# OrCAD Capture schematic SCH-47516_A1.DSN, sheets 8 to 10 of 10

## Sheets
8 Link2 ISP: size C
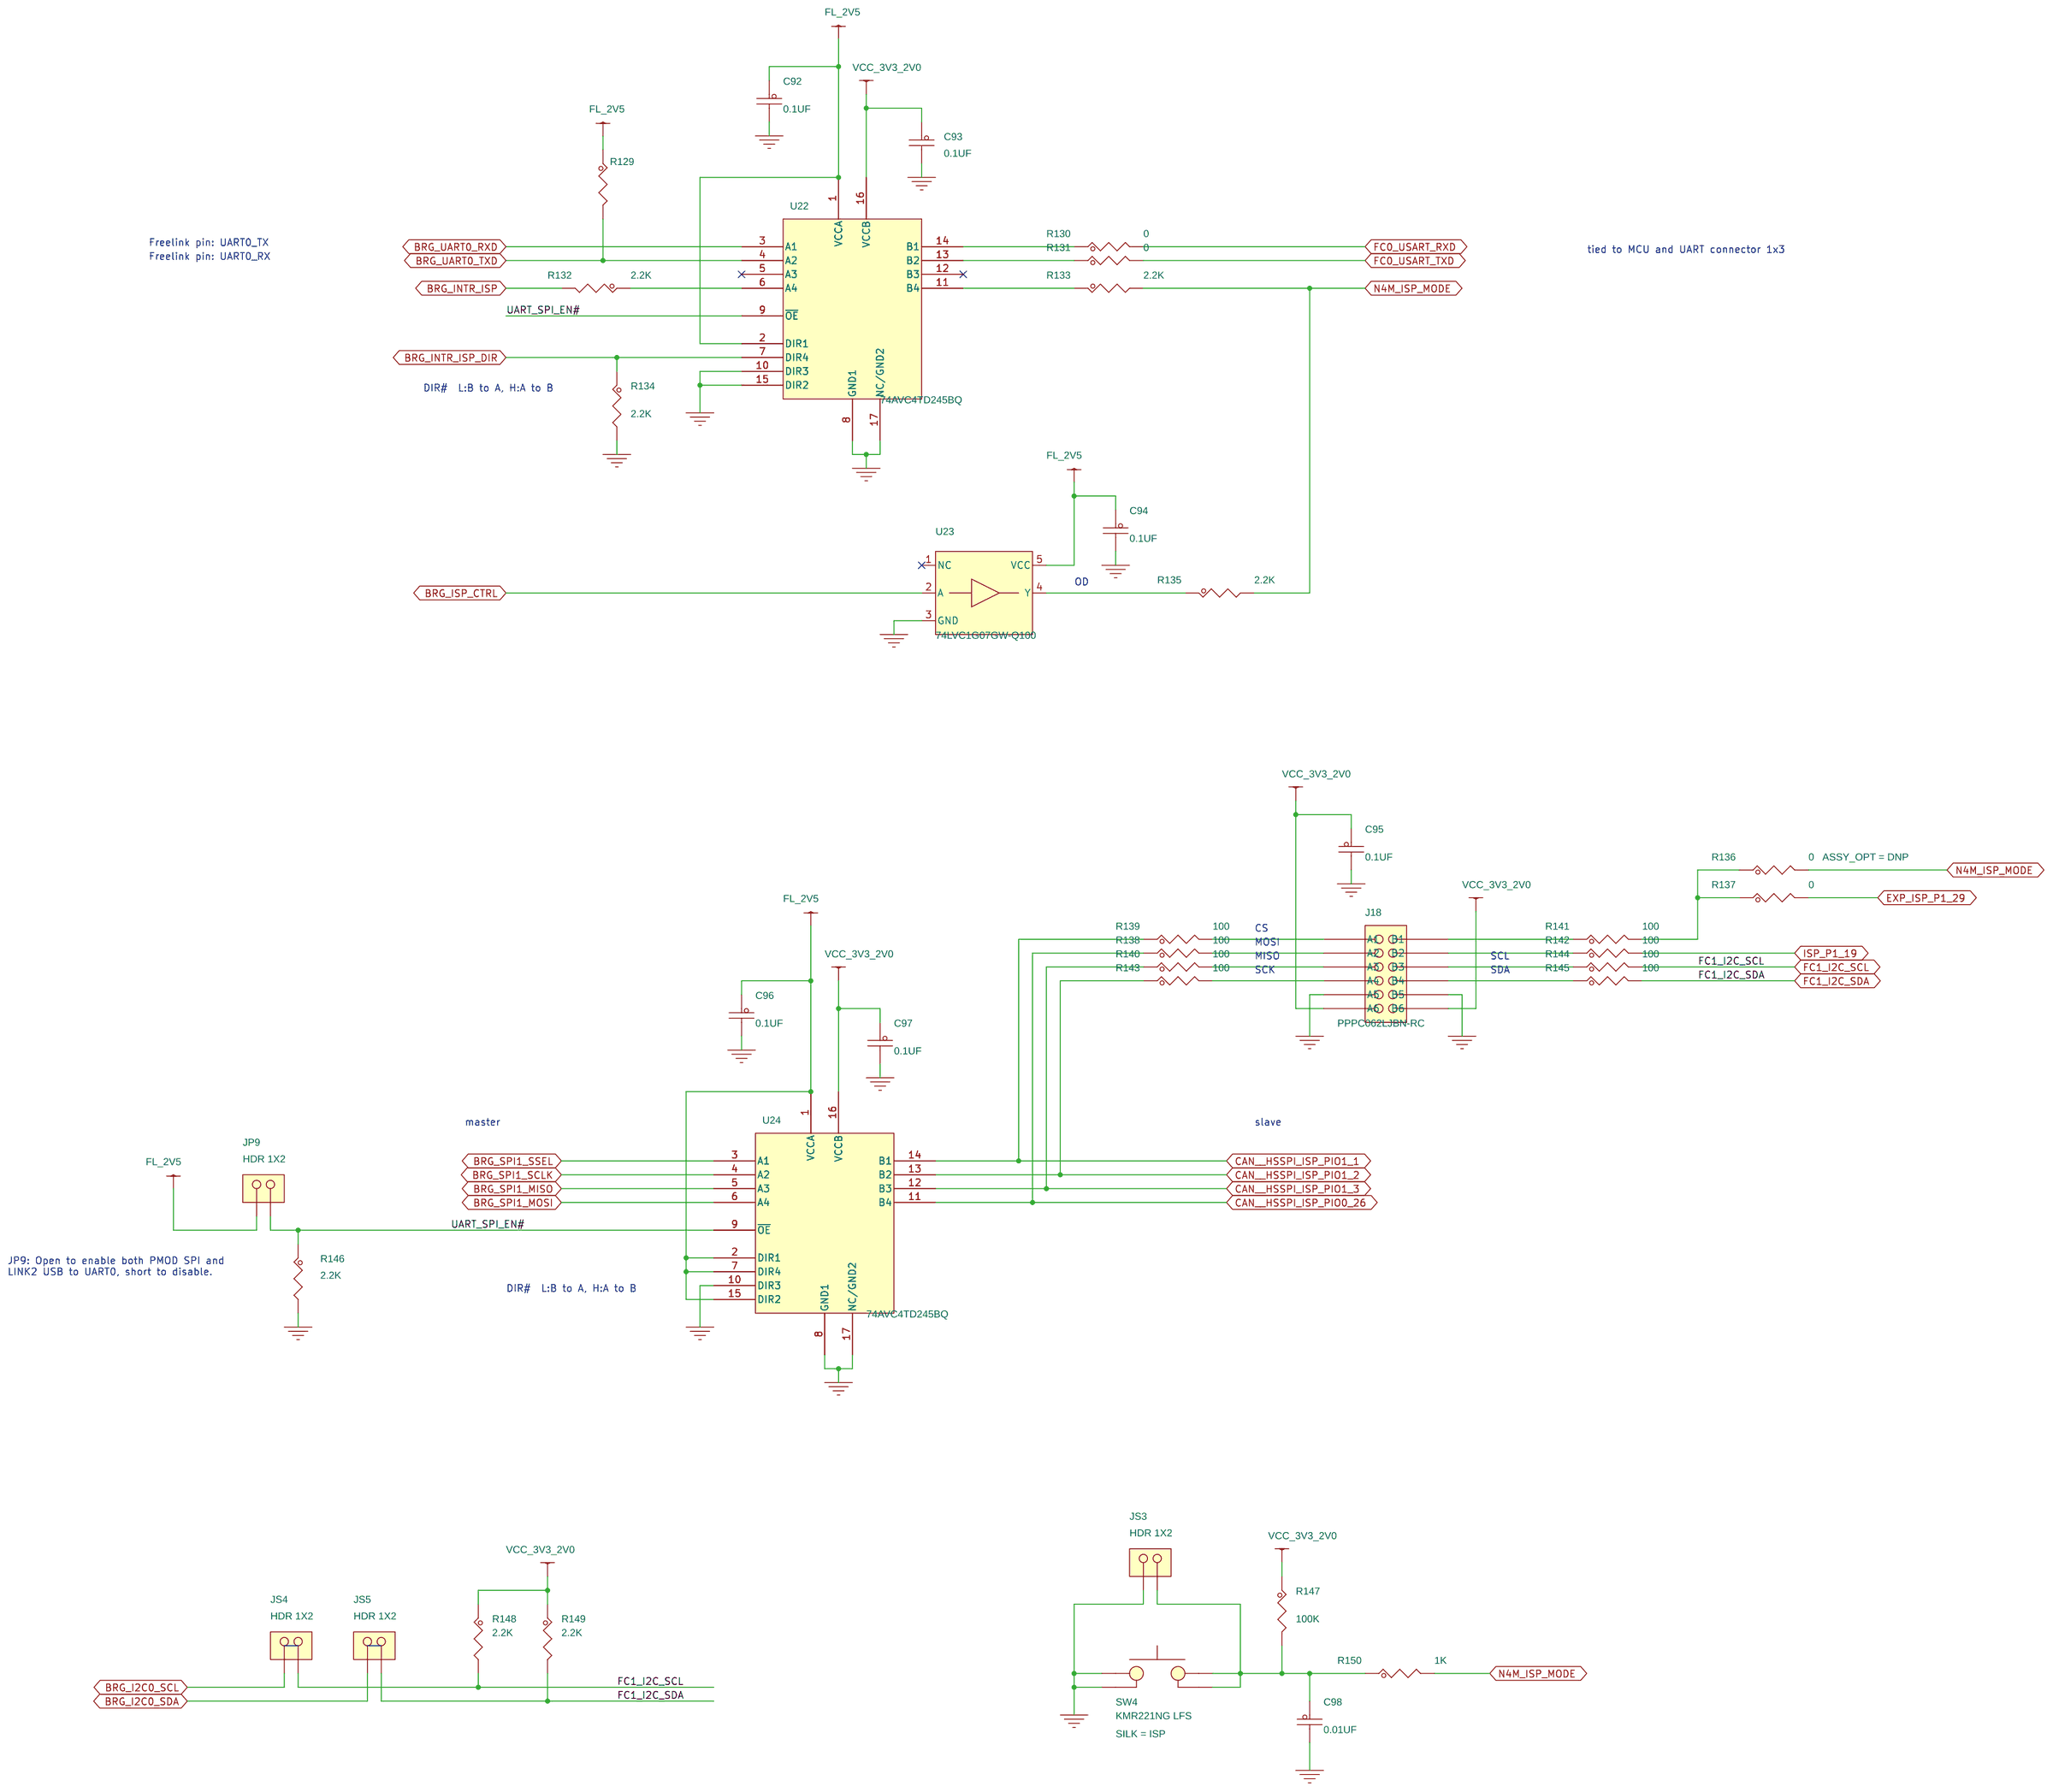
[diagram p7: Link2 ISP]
9 LPC55S06: size C
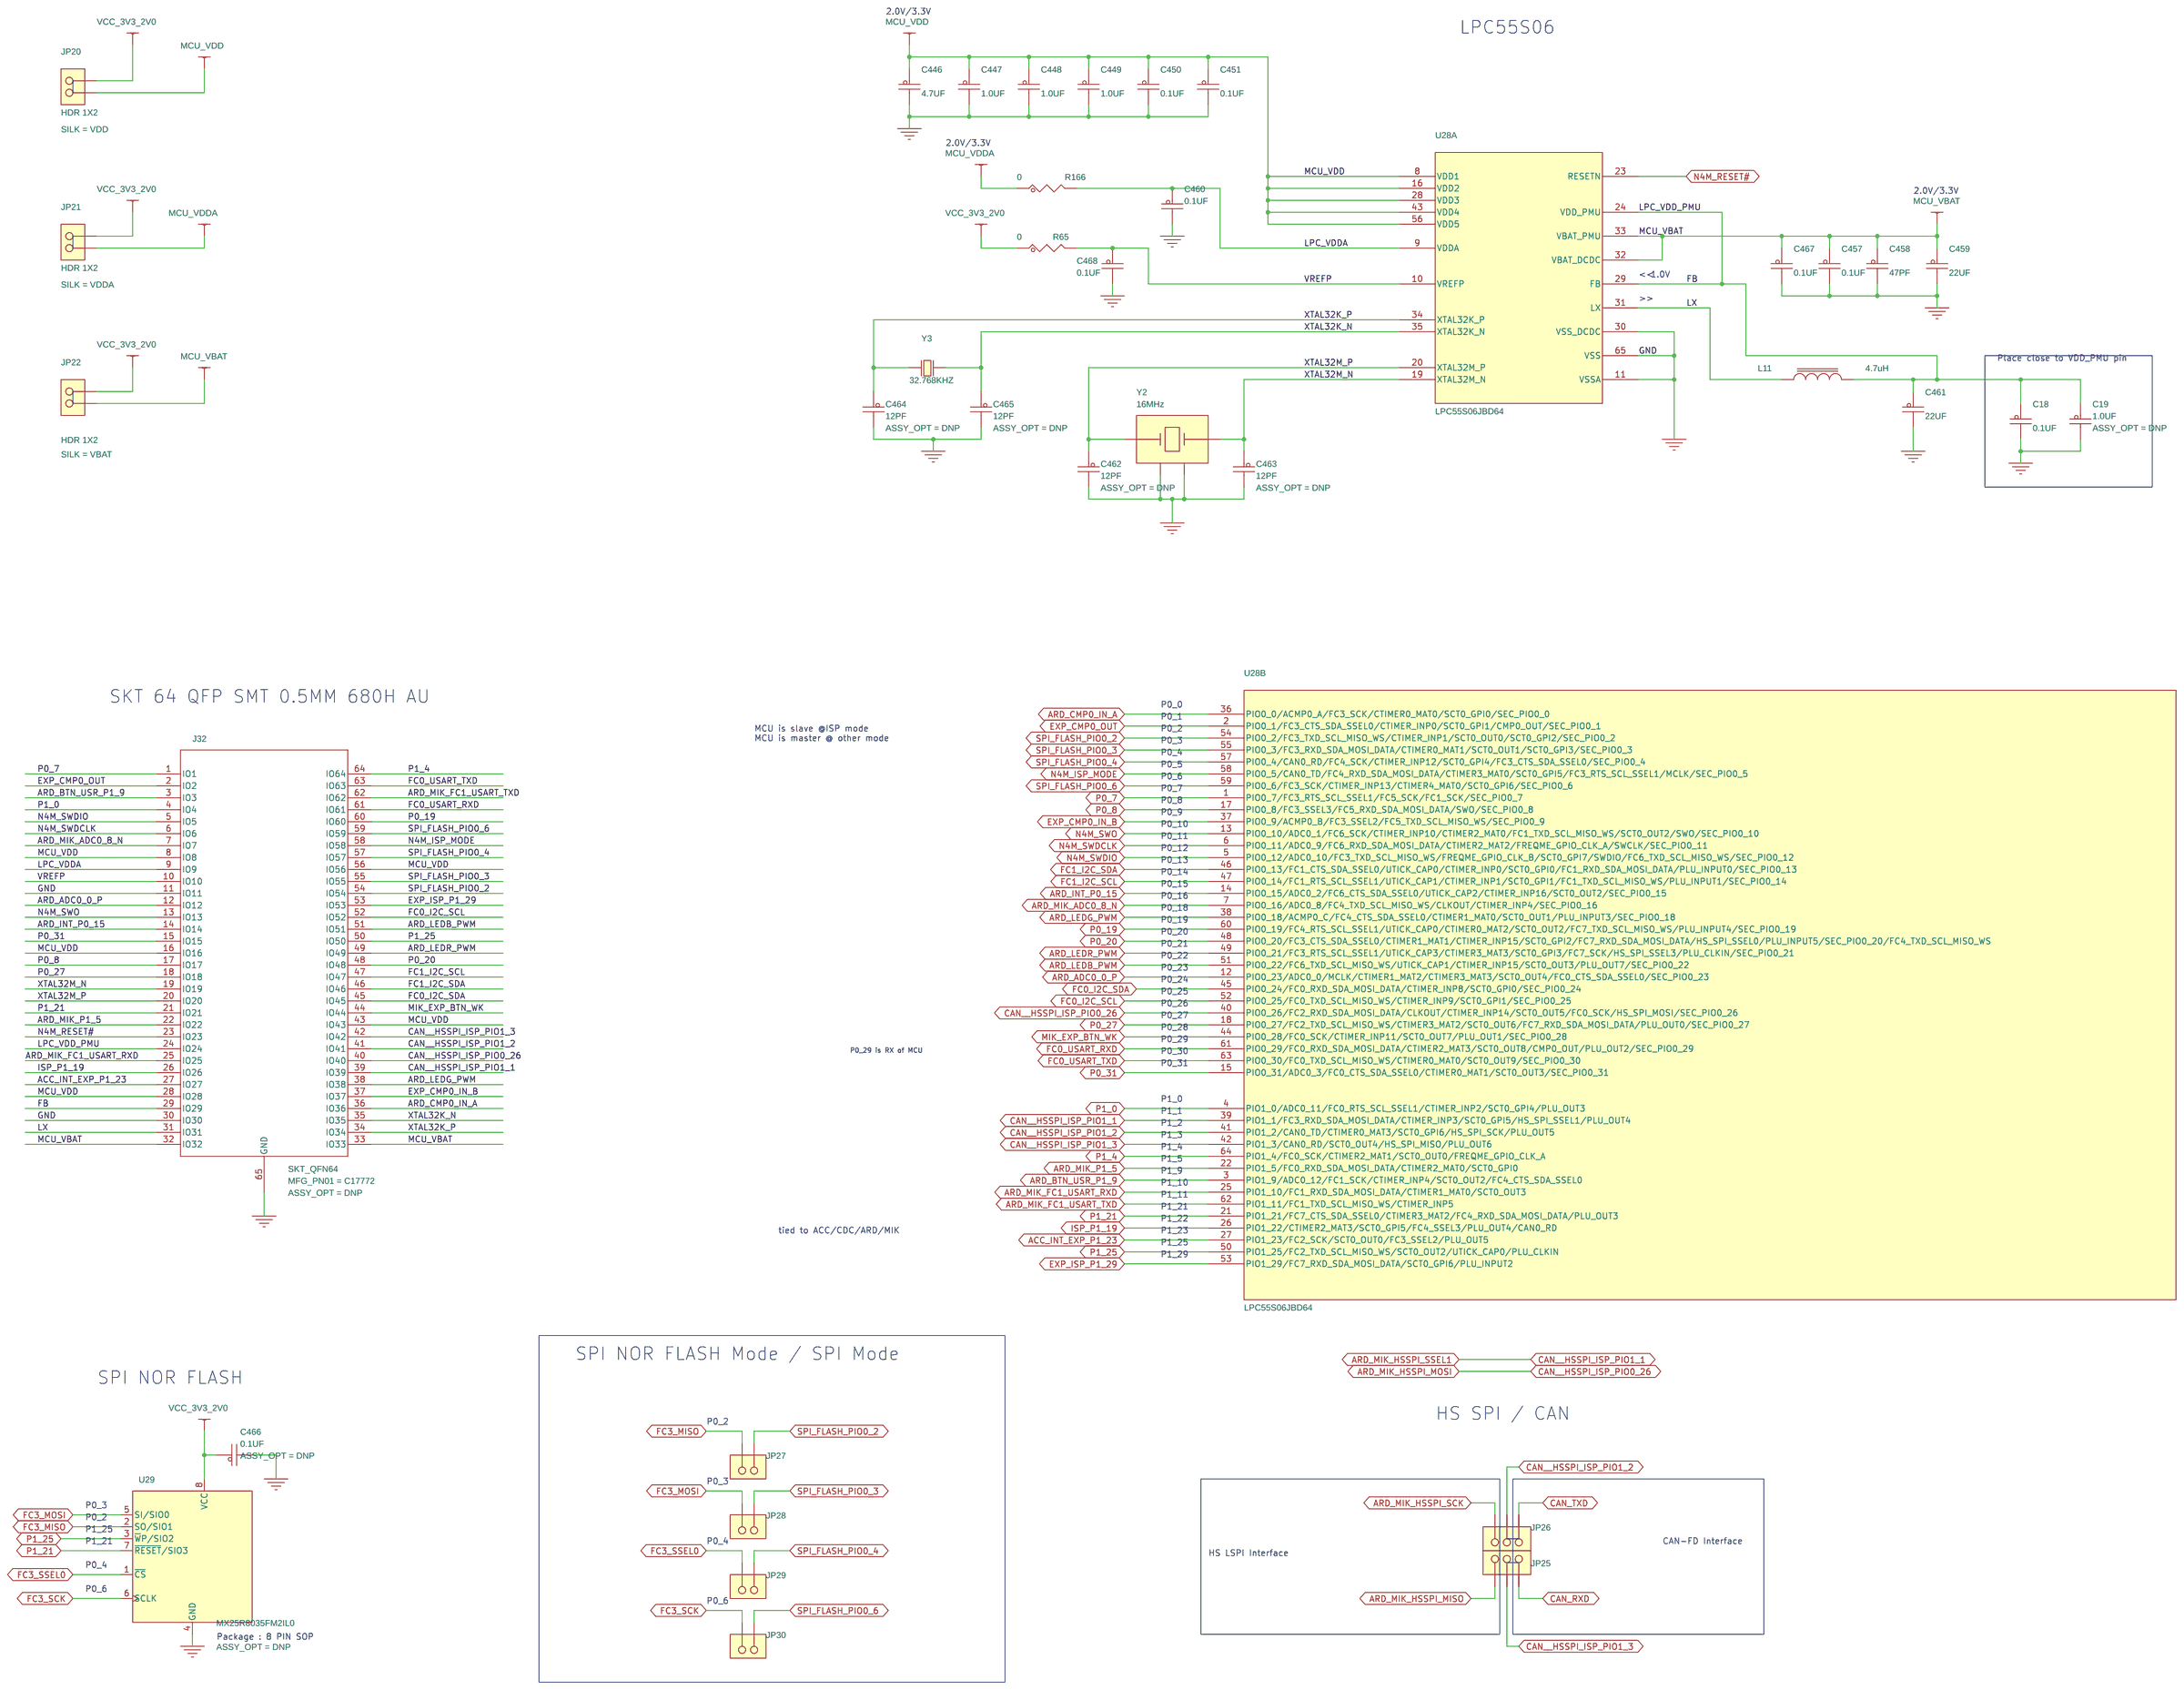
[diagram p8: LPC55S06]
10 Jumper & DNP Table
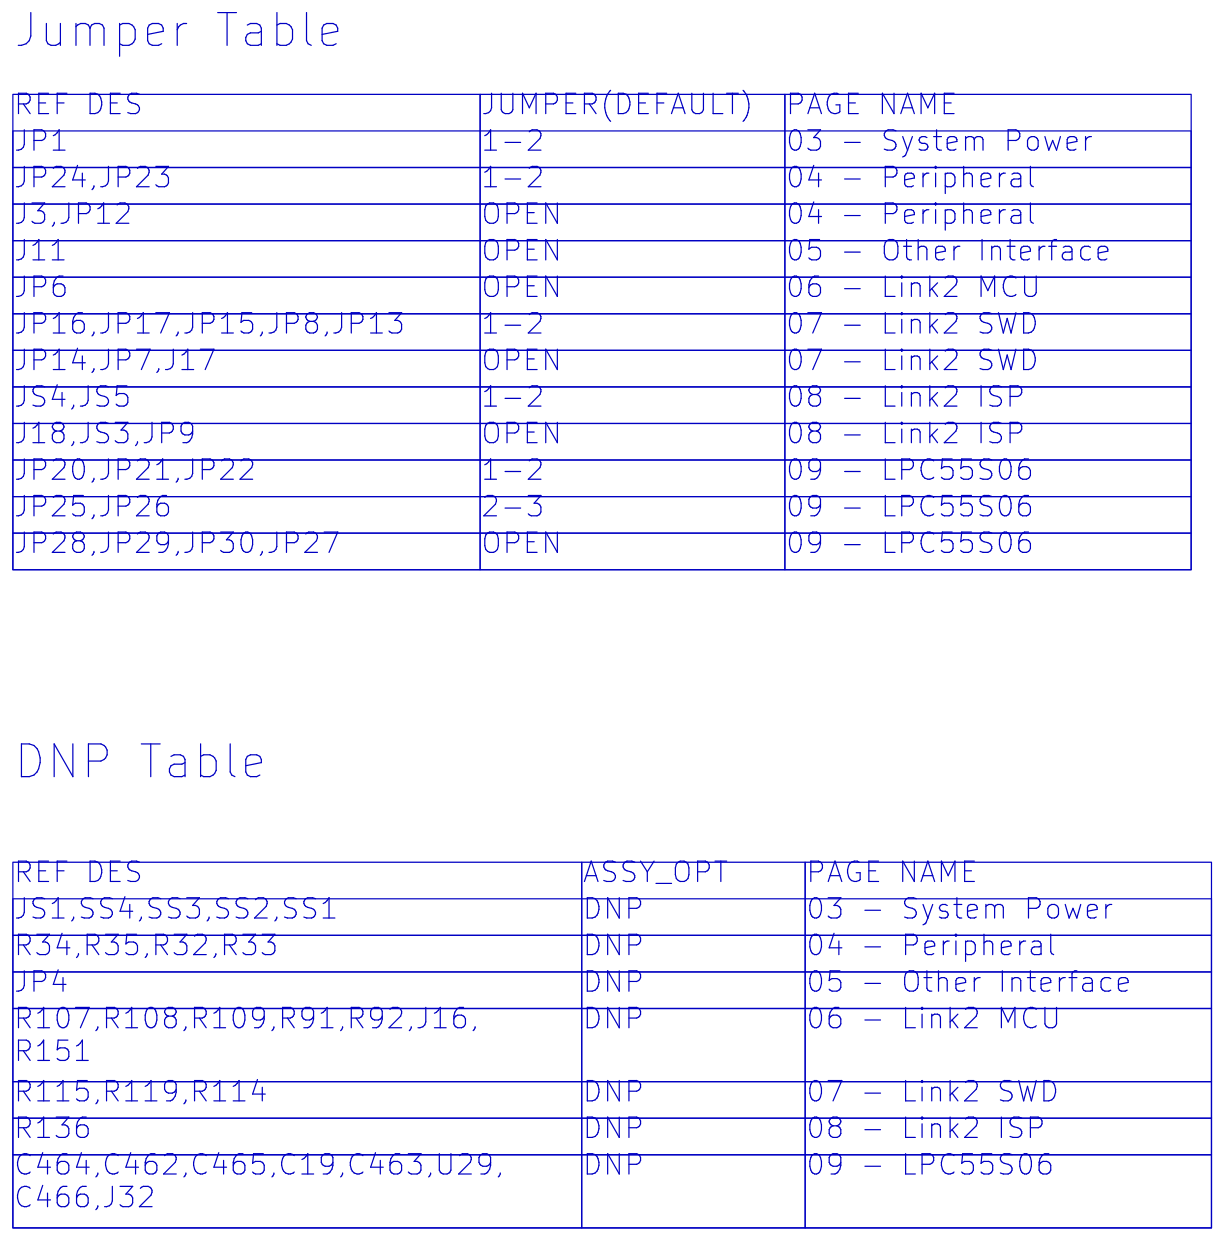
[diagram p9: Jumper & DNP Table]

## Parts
sheet Link2 ISP
C92  0.1UF  [CC0402_25]
C93  0.1UF  [CC0402_25]
C94  0.1UF  [CC0402_25]
C95  0.1UF  [CC0402_25]
C96  0.1UF  [CC0402_25]
C97  0.1UF  [CC0402_25]
C98  0.01UF  [CC0402_25]
J18  PPPC062LJBN-RC  [skt2x6_100_th_ra]
JP9  HDR 1X2  [HDR102]
JS3  HDR 1X2  [HDR102]
JS4  HDR 1X2  [HDR102]
JS5  HDR 1X2  [HDR102]
R129  10K  [0402_CC]
R130  0  [RC0402_25]
R131  0  [RC0402_25]
R132  2.2K  [RC0402_25]
R133  2.2K  [RC0402_25]
R134  2.2K  [RC0402_25]
R135  2.2K  [RC0402_25]
R136  0  [RC0402_25]
R137  0  [RC0402_25]
R138  100  [RC0402_25]
R139  100  [RC0402_25]
R140  100  [RC0402_25]
R141  100  [RC0402_25]
R142  100  [RC0402_25]
R143  100  [RC0402_25]
R144  100  [RC0402_25]
R145  100  [RC0402_25]
R146  2.2K  [RC0402_25]
R147  100K  [RC0402_25]
R148  2.2K  [RC0402_25]
R149  2.2K  [RC0402_25]
R150  1K  [RC0402_25]
SW4  KMR221NG LFS  [sw4_4p2x2p8_sm]
U22  74AVC4TD245BQ  [dhvqfn16_0p5_3p6x2p6]
U23  74LVC1G07GW-Q100  [sc70-5]
U24  74AVC4TD245BQ  [dhvqfn16_0p5_3p6x2p6]
sheet LPC55S06
C18  0.1UF  [0402_CC]
C19  1.0UF  [0402_CC]
C446  4.7UF  [cc0402_tol0p15]
C447  1.0UF  [0402_CC]
C448  1.0UF  [0402_CC]
C449  1.0UF  [0402_CC]
C450  0.1UF  [0402_CC]
C451  0.1UF  [0402_CC]
C457  0.1UF  [0402_CC]
C458  47PF  [0402_CC]
C459  22UF  [CC0603_OV]
C460  0.1UF  [0402_CC]
C461  22UF  [CC0603_OV]
C462  12PF  [0402_CC]
C463  12PF  [0402_CC]
C464  12PF  [0402_CC]
C465  12PF  [0402_CC]
C466  0.1UF  [0402_CC]
C467  0.1UF  [0402_CC]
C468  0.1UF  [0402_CC]
J32  SKT_QFN64  [skt_qfp64_0p5_22p25sq_mm]
JP20  HDR 1X2  [HDR102]
JP21  HDR 1X2  [HDR102]
JP22  HDR 1X2  [HDR102]
JP25  HDR_1X3  [HDR103]
JP26  HDR_1X3  [HDR103]
JP27  HDR 1X2 TH  [HDR_1X2]
JP28  HDR 1X2 TH  [HDR_1X2]
JP29  HDR 1X2 TH  [HDR_1X2]
JP30  HDR 1X2 TH  [HDR_1X2]
L11  4.7uH  [ind2_2722]
R65  0  [RC0402_25]
R166  0  [0402_CC]
U28  LPC55S06JBD64  [tqfp64_0p5_10x10_ep_3p31]  (sections A,B)
U29  MX25R8035FM2IL0  [SO8-25X75-200]
Y2  16MHz  [xtlosc4_3p2x2p5mm_sm]
Y3  32.768KHZ  [XTAL2-3p2x1p5-SM]

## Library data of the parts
C18 C92-C97 C450 C451 C457 C460 C467 C468 = CAP_NP: CAP CER 0.1UF 16V 10% X7R 0402; AGILE_PN: 150-75182; CAD_APPROVED: Yes; FPLIST: CC0402_25,CC0402_HD,0402_CC; HEIGHT: 0.635MM; MFG_NAME01: AVX; MFG_PN01: 0402YC104KAT2A; ROHS: Yes; Temp Range: -55°C to +125°C; Temp_Range: -55°C to +125°C; Tolerance: 10%; VOLTAGE: 16V
C98 = CAP_NP: CAP CER 0.01UF 16V 20% X7R 0402; AGILE_PN: 150-30082; CAD_APPROVED: Yes; FPLIST: CC0402_25,CC0402_HD,0402_CC; HEIGHT: 0.56MM; MFG_NAME01: AVX; MFG_PN01: 0402YC103MAT2A; Package Size: 0402; ROHS: Yes; Tolerance: 20%; VOLTAGE: 16V
J18 = CONN_HDR_6X2: CON 2X6 SKT RA TH 100MIL CTR 206H AU 124L; AGILE_PN: 210-80998; CAD_APPROVED: Yes; HEIGHT: 5.28 MM; Jumper (Default): OPEN; MFG_NAME01: SULLINS ELECTRONICS CORP; ROHS: Yes
JP9 JS3 = CONN_HDR_2X1: HDR 1X2 TH 100MIL SP 339H AU 98L; AGILE_PN: 210-81490; CAD_APPROVED: Yes; HEIGHT: 8.59MM; Jumper (Default): OPEN; MFG_NAME01: ANYTRONIC CORPORATION LIMITED; MFG_PN01: 0901S0202011N9T-31RF; ROHS: Yes; Temp Range: -55°C to +105°C; Temp_Range: -55°C to +105°C
JS4 JS5 = CONN_HDR_2X1: HDR 1X2 TH 100MIL SP 339H AU 98L; AGILE_PN: 210-81490; CAD_APPROVED: Yes; HEIGHT: 8.59MM; Jumper (Default): 1-2; MFG_NAME01: ANYTRONIC CORPORATION LIMITED; MFG_PN01: 0901S0202011N9T-31RF; ROHS: Yes; Temp Range: -55°C to +105°C; Temp_Range: -55°C to +105°C
R129 = RES: RES MF 10K 1/16W 5% 0402; AGILE_PN: 470-75557; CAD_APPROVED: Yes; FPLIST: RC0402_25,RC0402_HD,0402_CC; HEIGHT: 0.4 MM; MFG_NAME01: VISHAY INTERTECHNOLOGY; MFG_PN01: CRCW040210K0JNED; ROHS: Yes; TOL: 5%; Tolerance: 5%
R65 R130 R131 R137 R166 = RES: RES MF ZERO OHM 1/16W -- AEC-Q200 0402; AGILE_PN: 470-81849; CAD_APPROVED: Yes; FPLIST: RC0402_25,RC0402_HD,0402_CC; HEIGHT: 0.45 MM; MFG_NAME01: STACKPOLE ELECTRONICS; MFG_PN01: RMCF0402ZT0R00; ROHS: Yes
R132-R135 R146 R148 R149 = RES: RES MF 2.2K 1/16W 1% 0402; AGILE_PN: 470-78359; CAD_APPROVED: Yes; FPLIST: RC0402_25,RC0402_HD,0402_CC; HEIGHT: 0.4MM; MFG_NAME01: WALSIN TECHNOLOGY CORP.; MFG_PN01: WR04X2201FTL; ROHS: Yes; Temp Range: -55C to +155C; Temp_Range: -55C to +155C; Tolerance: 1%
R136 = RES: RES MF ZERO OHM 1/16W -- AEC-Q200 0402; AGILE_PN: 470-81849; ASSY_OPT: DNP; CAD_APPROVED: Yes; FPLIST: RC0402_25,RC0402_HD,0402_CC; HEIGHT: 0.45 MM; MFG_NAME01: STACKPOLE ELECTRONICS; MFG_PN01: RMCF0402ZT0R00; ROHS: Yes
R138-R145 = RES: RES MF 100 OHM 1/16W 5% 0402; AGILE_PN: 470-75591; CAD_APPROVED: Yes; FPLIST: RC0402_25,RC0402_HD,RC0402_X2,0402_CC; HEIGHT: 0.45mm; MFG_NAME01: NIC COMPONENTS CORP; MFG_PN01: NRCL04J101TRF; ROHS: Yes; Tolerance: 5%
R147 = RES: RES MF 100K 1/16W 1% 0402; AGILE_PN: 470-76240; CAD_APPROVED: Yes; FPLIST: RC0402_25,RC0402_HD,0402_CC; HEIGHT: 0.4MM; MFG_NAME01: NIC COMPONENTS CORP; MFG_PN01: NRCL04F1003TRF; ROHS: Yes; Tolerance: 1%
R150 = RES: RES MF 1.0K 1/16W 5% 0402; AGILE_PN: 470-82125; CAD_APPROVED: Yes; FPLIST: RC0402_25,RC0402_HD,RC0402_X2,0402_CC; HEIGHT: 0.4MM; MFG_NAME01: NIC COMPONENTS CORP; MFG_PN01: NRCL04J102TRF; ROHS: Yes; Temp Range: -55°C to +155°C; Temp_Range: -55°C to +155°C; Tolerance: 5%
SW4 = SW_PB_4P: SW SPST MOM PB NO 50MA 32V SMT; AGILE_PN: 510-78172; CAD_APPROVED: Yes; HEIGHT: 1.9 MM; MFG_NAME01: C&K COMPONENTS; ROHS: Yes; SILK: ISP; Temp Range: -40° C to +85° C; Temp_Range: -40° C to +85° C; VOLTAGE: 32V
U22 U24 = 74AVC4TD245BQ_DHVQFN16: IC DUAL SUPPLY XCVR XLTR 4BIT 0-3.6V DHVQFN16; 3D_Mechanical_Footprint_File: ftp://fcl.am.freescale.net/ALLEGRO/step/dhvqfn16_0p5_3p6x2p6.STEP; AGILE_PN: 312-81329; CAD_APPROVED: Yes; HEIGHT: 1MM; MFG_NAME01: NEXPERIA; MFG_PN01: 74AVC4TD245BQ,115; ROHS: Yes
U23 = 74AUP1G07GW: IC BUF NON-INV SGL 1.65-5.5V AEC-Q100 TSSOP5; AGILE_PN: 312-82179; CAD_APPROVED: Yes; HEIGHT: 1.1MM; MFG_NAME01: NEXPERIA; MFG_PN01: 74LVC1G07GW-Q100H; ROHS: Yes; Temp Range: -40 to +125C; Temp_Range: -40 to +125C; VOLTAGE: 1.65-5.5V
C19 = CAP_NP: CAP CER 1.0UF 10V 10% X5R 0402; AGILE_PN: 150-75772; ASSY_OPT: DNP; CAD_APPROVED: Yes; FPLIST: CC0402_25,CC0402_HD,0402_CC; HEIGHT: 0.6MM; MFG_NAME01: YAGEO AMERICA; MFG_PN01: CC0402KRX5R6BB105; Package Size: 0402; ROHS: Yes; VOLTAGE: 10V; voltage rating: 10V
C446 = CAP_NP: CAP CER 4.7uF 10V 20% X5R 0402_WIDE; AGILE_PN: 150-79667; CAD_APPROVED: Yes; FPLIST: CC0402_25,CC0402_HD,0402_CC; HEIGHT: 0.7 MM; MFG_NAME01: MURATA; MFG_PN01: GRM155R61A475MEAA; Package Size: 0402; ROHS: Yes; Temp Range: -55 to 85; Temp_Range: -55 to 85; Tolerance: 20%; VOLTAGE: 10V
C447-C449 = CAP_NP: CAP CER 1.0UF 10V 10% X5R 0402; AGILE_PN: 150-75772; CAD_APPROVED: Yes; FPLIST: CC0402_25,CC0402_HD,0402_CC; HEIGHT: 0.6MM; MFG_NAME01: YAGEO AMERICA; MFG_PN01: CC0402KRX5R6BB105; Package Size: 0402; ROHS: Yes; VOLTAGE: 10V; voltage rating: 10V
C458 = CAP_NP: CAP CER 47PF 16V 5% C0G 0402; AGILE_PN: 150-75268; CAD_APPROVED: YES; FPLIST: CC0402_25,CC0402_HD,0402_CC; HEIGHT: 0.56MM; MFG_NAME01: AVX; MFG_PN01: 0402YA470JAT2A; Package Size: 0402; Package Type: 7; ROHS: Yes; Tolerance: 5%; VOLTAGE: 16V
C459 C461 = CAP_NP: CAP CER 22UF 6.3V 20% X5R 0603; AGILE_PN: 150-78467; CAD_APPROVED: Yes; FPLIST: CC0603_OV,CC0603,0603_CC; HEIGHT: 1MM; MFG_NAME01: SAMSUNG; MFG_PN01: CL10A226MQ8NRNE; Package Size: 0603; ROHS: Yes; Tolerance: 20%; VOLTAGE: 6.3V
C462-C465 = CAP_NP: CAP CER 12PF 25V 5% C0G 0402; AGILE_PN: 150-30180; ASSY_OPT: DNP; CAD_APPROVED: Yes; FPLIST: CC0402_25,CC0402_HD,0402_CC; HEIGHT: 0.55 MM; MFG_NAME01: KEMET; MFG_PN01: C0402C120J3GAC7867; ROHS: Yes; Tolerance: 5%
C466 = CAP_NP: CAP CER 0.1UF 16V 10% X7R 0402; AGILE_PN: 150-75182; ASSY_OPT: DNP; CAD_APPROVED: Yes; FPLIST: CC0402_25,CC0402_HD,0402_CC; HEIGHT: 0.635MM; MFG_NAME01: AVX; MFG_PN01: 0402YC104KAT2A; ROHS: Yes; Temp Range: -55°C to +125°C; Temp_Range: -55°C to +125°C; Tolerance: 10%; VOLTAGE: 16V
J32 = QFPSOCKET65: SKT 64 QFP SMT 0.5MM 680H AU; AGILE_PN: 211-81107; ASSY_OPT: DNP; CAD_APPROVED: Yes; HEIGHT: 17.26 MM; MFG_NAME01: Ironwood Electronics, Inc.; MFG_PN01: C17772; Package Type: SOCKET\QFP; ROHS: Yes; Temp Range: -55°C to +180°C
JP20 = CONN_HDR_2X1: HDR 1X2 TH 100MIL SP 339H AU 98L; AGILE_PN: 210-81490; CAD_APPROVED: Yes; HEIGHT: 8.59MM; Jumper (Default): 1-2; MFG_NAME01: ANYTRONIC CORPORATION LIMITED; MFG_PN01: 0901S0202011N9T-31RF; ROHS: Yes; SILK: VDD; Temp Range: -55°C to +105°C; Temp_Range: -55°C to +105°C
JP21 = CONN_HDR_2X1: HDR 1X2 TH 100MIL SP 339H AU 98L; AGILE_PN: 210-81490; CAD_APPROVED: Yes; HEIGHT: 8.59MM; Jumper (Default): 1-2; MFG_NAME01: ANYTRONIC CORPORATION LIMITED; MFG_PN01: 0901S0202011N9T-31RF; ROHS: Yes; SILK: VDDA; Temp Range: -55°C to +105°C; Temp_Range: -55°C to +105°C
JP22 = CONN_HDR_2X1: HDR 1X2 TH 100MIL SP 339H AU 98L; AGILE_PN: 210-81490; CAD_APPROVED: Yes; HEIGHT: 8.59MM; Jumper (Default): 1-2; MFG_NAME01: ANYTRONIC CORPORATION LIMITED; MFG_PN01: 0901S0202011N9T-31RF; ROHS: Yes; SILK: VBAT; Temp Range: -55°C to +105°C; Temp_Range: -55°C to +105°C
JP25 JP26 = CONN_HDR_3X1: HDR 1X3 TH 100MIL SP 338H AU 98L; AGILE_PN: 210-81491; CAD_APPROVED: Yes; HEIGHT: 8.59MM; Jumper (Default): 2-3; MFG_NAME01: ANYTRONIC CORPORATION LIMITED; MFG_PN01: 0901S0203011N9T-31RF; ROHS: Yes; Temp Range: -55°C to +105°C; Temp_Range: -55°C to +105°C
JP27-JP30 = CONN_HDR_2X1: HDR 1X2 TH 100MIL SP 339H AU 98L; AGILE_PN: 210-75439; CAD_APPROVED: YES; FPLIST: HDR_1X2,SH_HDR102_BOTTOM; HEIGHT: 8.71 MM; Jumper (Default): OPEN; MFG_NAME01: SAMTEC; MFG_PN01: TSW-102-07-G-S; ROHS: Yes; Temp Range: -55°C to +125°C
L11 = INDUCTOR_FERRITE_A: IND PWR SHIELDED 4.7uH@1MHZ 1.55A 20% AEC-Q200 SMD; AGILE_PN: 180-78872; CAD_APPROVED: Yes; HEIGHT: 1.2MM; MFG_NAME01: BOURNS; MFG_PN01: SRP2512A-4R7M; PART_TYPE: INDUCTOR\POWER; Package Size: 2.5x2x1.2mm; ROHS: Yes; Temp Range: -40°C to 125°C; Temp_Range: -40°C to 125°C; Tolerance: 20%
U28 = LPC55S06JBD_HTQFP64: IC MCU 32BIT ARM  256KB FLASH 96KB SRAM 1.8-3.6V HTQFP64; AGILE_PN: 344-02449; CAD_APPROVED: Yes; HEIGHT: 1.2MM; MFG_NAME01: NXP SEMICONDUCTORS; ROHS: Yes; Supply Voltage: 1.8-3.6V; Temp Range: -40  to +105C
U29 = MX25R6435FM2IL0: IC MEM FLASH NOR 8Mb SPI 33MHZ 1.65-3.6V SO8W; AGILE_PN: 342-00858; ASSY_OPT: DNP; CAD_APPROVED: Yes; HEIGHT: 2.16MM; MFG_NAME01: MACRONIX INTERNATIONAL CO., LTD; Package Size: 8-SOIC (0.209", 5.30mm Width); ROHS: Yes; Supply Voltage: 1.65V ~ 3.6V; Temp Range: -40  °C to +85 °C; VOLTAGE: 1.65V-3.6V
Y2 = XTAL_13: XTAL 16MHz 8pF AEC-Q200 SMD; 3D_Mechanical_Footprint_File: ftp://fcl.am.freescale.net/ALLEGRO/step/xtlosc4_3p2x2p5mm_sm.STEP; AGILE_PN: TMP-CIP-5707; CAD_APPROVED: Yes; Frequency Tolerance: 15ppm; HEIGHT: 0.6MM; MFG_NAME01: NDK; MFG_PN01: NX3225SA-16.000M-STD-CRS-2; PRE_APN: 230-78449; Package Size: 0.126" L x 0.098" W (3.20mm x 2.50mm); ROHS: Yes; Temp Range: -40°C to +125°C
Y3 = CRYSTAL: XTAL 32.768KHZ 7PF 20PPM -- SMT; AGILE_PN: 230-78102; CAD_APPROVED: Yes; HEIGHT: 0.9MM; MFG_NAME01: EPSON ELECTRONICS; MFG_PN01: FC-135 32.7680KA-AG3; ROHS: Yes

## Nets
GND: C18.2 C19.2 C92.2 C93.2 C94.2 C95.2 C96.2 C97.2 C98.2 C446.2 C447.2 C448.2 C449.2 C450.2 C451.2 C457.2 C458.2 C459.2 C460.2 C461.2 C462.2 C463.2 C464.2 C465.2 C466.2 C467.2 C468.2 J18.9(A5) J18.10(B5) J32.11(IO11) J32.30(IO30) J32.65(GND) JS3.2 R134.2 R146.2 SW4.3 SW4.4 U22.8(GND1) U22.10(DIR3) U22.15(DIR2) U22.17(NC/GND2) U23.3(GND) U24.8(GND1) U24.10(DIR3) U24.17(NC/GND2) U28.11(VSSA) U28.30(VSS_DCDC) U28.65(VSS) U29.4(GND) Y2.2 Y2.4 ; also on sheet 3 4 5 6 7
VCC_3V3_2V0: C93.1 C95.1 C97.1 C466.1 J18.11(A6) J18.12(B6) JP20.1 JP21.1 JP22.1 R65.1 R147.1 R148.1 R149.1 U22.16(VCCB) U24.16(VCCB) U29.8(VCC) ; also on sheet 3 4 5 7
ACC_INT_EXP_P1_23: J32.27(IO27) U28.27(PIO1_23/FC2_SCK/SCT0_OUT0/FC3_SSEL2/PLU_OUT5) ; also on sheet 4 5
ARD_ADC0_0_P: J32.12(IO12) U28.12(PIO0_23/ADC0_0/MCLK/CTIMER1_MAT2/CTIMER3_MAT3/SCT0_OUT4/FC0_CTS_SDA_SSEL0/SEC_PIO0_23) ; also on sheet 5
ARD_BTN_USR_P1_9: J32.3(IO3) U28.3(PIO1_9/ADC0_12/FC1_SCK/CTIMER_INP4/SCT0_OUT2/FC4_CTS_SDA_SSEL0) ; also on sheet 4 5
ARD_CMP0_IN_A: J32.36(IO36) U28.36(PIO0_0/ACMP0_A/FC3_SCK/CTIMER0_MAT0/SCT0_GPI0/SEC_PIO0_0) ; also on sheet 5
ARD_INT_P0_15: J32.14(IO14) U28.14(PIO0_15/ADC0_2/FC6_CTS_SDA_SSEL0/UTICK_CAP2/CTIMER_INP16/SCT0_OUT2/SEC_PIO0_15) ; also on sheet 5
ARD_LEDB_PWM: J32.51(IO51) U28.51(PIO0_22/FC6_TXD_SCL_MISO_WS/UTICK_CAP1/CTIMER_INP15/SCT0_OUT3/PLU_OUT7/SEC_PIO0_22) ; also on sheet 4 5
ARD_LEDG_PWM: J32.38(IO38) U28.38(PIO0_18/ACMP0_C/FC4_CTS_SDA_SSEL0/CTIMER1_MAT0/SCT0_OUT1/PLU_INPUT3/SEC_PIO0_18) ; also on sheet 4 5
ARD_LEDR_PWM: J32.49(IO49) U28.49(PIO0_21/FC3_RTS_SCL_SSEL1/UTICK_CAP3/CTIMER3_MAT3/SCT0_GPI3/FC7_SCK/HS_SPI_SSEL3/PLU_CLKIN/SEC_PIO0_21) ; also on sheet 4 5
ARD_MIK_ADC0_8_N: J32.7(IO7) U28.7(PIO0_16/ADC0_8/FC4_TXD_SCL_MISO_WS/CLKOUT/CTIMER_INP4/SEC_PIO0_16) ; also on sheet 5
ARD_MIK_FC1_USART_RXD: J32.25(IO25) U28.25(PIO1_10/FC1_RXD_SDA_MOSI_DATA/CTIMER1_MAT0/SCT0_OUT3) ; also on sheet 5
ARD_MIK_FC1_USART_TXD: J32.62(IO62) U28.62(PIO1_11/FC1_TXD_SCL_MISO_WS/CTIMER_INP5) ; also on sheet 5
ARD_MIK_HSSPI_MISO: JP25.1 ; also on sheet 5
ARD_MIK_HSSPI_MOSI: J32.40(IO40) R138.1 U24.11(B4) U28.40(PIO0_26/FC2_RXD_SDA_MOSI_DATA/CLKOUT/CTIMER_INP14/SCT0_OUT5/FC0_SCK/HS_SPI_MOSI/SEC_PIO0_26) ; also on sheet 5
ARD_MIK_HSSPI_SCK: JP26.1 ; also on sheet 5
ARD_MIK_HSSPI_SSEL1: J32.39(IO39) R139.1 U24.14(B1) U28.39(PIO1_1/FC3_RXD_SDA_MOSI_DATA/CTIMER_INP3/SCT0_GPI5/HS_SPI_SSEL1/PLU_OUT4) ; also on sheet 5
ARD_MIK_P1_5: J32.22(IO22) U28.22(PIO1_5/FC0_RXD_SDA_MOSI_DATA/CTIMER2_MAT0/SCT0_GPI0) ; also on sheet 5
BRG_I2C0_SCL: JS4.1 ; also on sheet 6
BRG_I2C0_SDA: JS5.1 ; also on sheet 6
BRG_INTR_ISP: R132.2 ; also on sheet 6
BRG_INTR_ISP_DIR: R134.1 U22.7(DIR4) ; also on sheet 6
BRG_ISP_CTRL: U23.2(A) ; also on sheet 6
BRG_SPI1_MISO: U24.5(A3) ; also on sheet 6
BRG_SPI1_MOSI: U24.6(A4) ; also on sheet 6
BRG_SPI1_SCLK: U24.4(A2) ; also on sheet 6
BRG_SPI1_SSEL: U24.3(A1) ; also on sheet 6
BRG_UART0_RXD: U22.3(A1) ; also on sheet 6
BRG_UART0_TXD: R129.2 U22.4(A2) ; also on sheet 6
CAN__HSSPI_ISP_PIO1_2: J32.41(IO41) JP26.2 R143.1 U24.13(B2) U28.41(PIO1_2/CAN0_TD/CTIMER0_MAT3/SCT0_GPI6/HS_SPI_SCK/PLU_OUT5)
CAN__HSSPI_ISP_PIO1_3: J32.42(IO42) JP25.2 R140.1 U24.12(B3) U28.42(PIO1_3/CAN0_RD/SCT0_OUT4/HS_SPI_MISO/PLU_OUT6)
CAN_RXD: JP25.3 ; also on sheet 4
CAN_TXD: JP26.3 ; also on sheet 4
EXP_CMP0_IN_B: J32.37(IO37) U28.37(PIO0_9/ACMP0_B/FC3_SSEL2/FC5_TXD_SCL_MISO_WS/SEC_PIO0_9) ; also on sheet 5
EXP_CMP0_OUT: J32.2(IO2) U28.2(PIO0_1/FC3_CTS_SDA_SSEL0/CTIMER_INP0/SCT0_GPI1/CMP0_OUT/SEC_PIO0_1) ; also on sheet 5
EXP_ISP_P1_29: J32.53(IO53) R137.2 U28.53(PIO1_29/FC7_RXD_SDA_MOSI_DATA/SCT0_GPI6/PLU_INPUT2) ; also on sheet 5
FB: C18.1 C19.1 C461.1 J32.24(IO24) J32.29(IO29) L11.2 U28.24(VDD_PMU) U28.29(FB)
FC0_I2C_SCL: J32.52(IO52) U28.52(PIO0_25/FC0_TXD_SCL_MISO_WS/CTIMER_INP9/SCT0_GPI1/SEC_PIO0_25) ; also on sheet 5
FC0_I2C_SDA: J32.45(IO45) U28.45(PIO0_24/FC0_RXD_SDA_MOSI_DATA/CTIMER_INP8/SCT0_GPI0/SEC_PIO0_24) ; also on sheet 5
FC0_USART_RXD: J32.61(IO61) R130.2 U28.61(PIO0_29/FC0_RXD_SDA_MOSI_DATA/CTIMER2_MAT3/SCT0_OUT8/CMP0_OUT/PLU_OUT2/SEC_PIO0_29) ; also on sheet 4
FC0_USART_TXD: J32.63(IO63) R131.2 U28.63(PIO0_30/FC0_TXD_SCL_MISO_WS/CTIMER0_MAT0/SCT0_OUT9/SEC_PIO0_30) ; also on sheet 4 5
FC1_I2C_SCL: J32.47(IO47) JS4.2 R144.2 R148.2 U28.47(PIO0_14/FC1_RTS_SCL_SSEL1/UTICK_CAP1/CTIMER_INP1/SCT0_GPI1/FC1_TXD_SCL_MISO_WS/PLU_INPUT1/SEC_PIO0_14) ; also on sheet 5
FC1_I2C_SDA: J32.46(IO46) JS5.2 R145.2 R149.2 U28.46(PIO0_13/FC1_CTS_SDA_SSEL0/UTICK_CAP0/CTIMER_INP0/SCT0_GPI0/FC1_RXD_SDA_MOSI_DATA/PLU_INPUT0/SEC_PIO0_13) ; also on sheet 5
FC3_MISO: JP27.1 U29.2(SO/SIO1)
FC3_MOSI: JP28.1 U29.5(SI/SIO0)
FC3_SCK: JP30.1 U29.6(SCLK)
FC3_SSEL0: JP29.1 U29.1(~{CS})
FL_2V5: C92.1 C94.1 C96.1 JP9.1 R129.1 U22.1(VCCA) U22.2(DIR1) U23.5(VCC) U24.1(VCCA) U24.2(DIR1) U24.7(DIR4) U24.15(DIR2) ; also on sheet 3 6 7
ISP_P1_19: J32.26(IO26) R142.2 U28.26(PIO1_22/CTIMER2_MAT3/SCT0_GPI5/FC4_SSEL3/PLU_OUT4/CAN0_RD)
LPC_VDDA: C460.1 J32.9(IO9) R166.2 U28.9(VDDA)
LX: J32.31(IO31) L11.1 U28.31(LX)
MCU_VBAT: C457.1 C458.1 C459.1 C467.1 J32.32(IO32) J32.33(IO33) JP22.2 U28.32(VBAT_DCDC) U28.33(VBAT_PMU)
MCU_VDD: C446.1 C447.1 C448.1 C449.1 C450.1 C451.1 J32.8(IO8) J32.16(IO16) J32.28(IO28) J32.43(IO43) J32.56(IO56) JP20.2 U28.8(VDD1) U28.16(VDD2) U28.28(VDD3) U28.43(VDD4) U28.56(VDD5)
MCU_VDDA: JP21.2 R166.1
MIK_EXP_BTN_WK: J32.44(IO44) U28.44(PIO0_28/FC0_SCK/CTIMER_INP11/SCT0_OUT7/PLU_OUT1/SEC_PIO0_28) ; also on sheet 4 5
N4M_ISP_MODE: J32.58(IO58) R133.2 R135.2 R136.2 R150.2 U28.58(PIO0_5/CAN0_TD/FC4_RXD_SDA_MOSI_DATA/CTIMER3_MAT0/SCT0_GPI5/FC3_RTS_SCL_SSEL1/MCLK/SEC_PIO0_5) ; also on sheet 5 7
N4M_RESET#: J32.23(IO23) U28.23(RESETN) ; also on sheet 4 5 7
N4M_SWDCLK: J32.6(IO6) U28.6(PIO0_11/ADC0_9/FC6_RXD_SDA_MOSI_DATA/CTIMER2_MAT2/FREQME_GPIO_CLK_A/SWCLK/SEC_PIO0_11) ; also on sheet 5 7
N4M_SWDIO: J32.5(IO5) U28.5(PIO0_12/ADC0_10/FC3_TXD_SCL_MISO_WS/FREQME_GPIO_CLK_B/SCT0_GPI7/SWDIO/FC6_TXD_SCL_MISO_WS/SEC_PIO0_12) ; also on sheet 5 7
N4M_SWO: J32.13(IO13) U28.13(PIO0_10/ADC0_1/FC6_SCK/CTIMER_INP10/CTIMER2_MAT0/FC1_TXD_SCL_MISO_WS/SCT0_OUT2/SWO/SEC_PIO0_10) ; also on sheet 5 7
P0_7: J32.1(IO1) U28.1(PIO0_7/FC3_RTS_SCL_SSEL1/FC5_SCK/FC1_SCK/SEC_PIO0_7) ; also on sheet 5
P0_8: J32.17(IO17) U28.17(PIO0_8/FC3_SSEL3/FC5_RXD_SDA_MOSI_DATA/SWO/SEC_PIO0_8) ; also on sheet 5
P0_19: J32.60(IO60) U28.60(PIO0_19/FC4_RTS_SCL_SSEL1/UTICK_CAP0/CTIMER0_MAT2/SCT0_OUT2/FC7_TXD_SCL_MISO_WS/PLU_INPUT4/SEC_PIO0_19) ; also on sheet 5
P0_20: J32.48(IO48) U28.48(PIO0_20/FC3_CTS_SDA_SSEL0/CTIMER1_MAT1/CTIMER_INP15/SCT0_GPI2/FC7_RXD_SDA_MOSI_DATA/HS_SPI_SSEL0/PLU_INPUT5/SEC_PIO0_20/FC4_TXD_SCL_MISO_WS) ; also on sheet 5
P0_27: J32.18(IO18) U28.18(PIO0_27/FC2_TXD_SCL_MISO_WS/CTIMER3_MAT2/SCT0_OUT6/FC7_RXD_SDA_MOSI_DATA/PLU_OUT0/SEC_PIO0_27) ; also on sheet 5
P0_31: J32.15(IO15) U28.15(PIO0_31/ADC0_3/FC0_CTS_SDA_SSEL0/CTIMER0_MAT1/SCT0_OUT3/SEC_PIO0_31) ; also on sheet 5
P1_0: J32.4(IO4) U28.4(PIO1_0/ADC0_11/FC0_RTS_SCL_SSEL1/CTIMER_INP2/SCT0_GPI4/PLU_OUT3) ; also on sheet 5
P1_4: J32.64(IO64) U28.64(PIO1_4/FC0_SCK/CTIMER2_MAT1/SCT0_OUT0/FREQME_GPIO_CLK_A) ; also on sheet 5
P1_21: J32.21(IO21) U28.21(PIO1_21/FC7_CTS_SDA_SSEL0/CTIMER3_MAT2/FC4_RXD_SDA_MOSI_DATA/PLU_OUT3) U29.7(~{RESET}/SIO3) ; also on sheet 5
P1_25: J32.50(IO50) U28.50(PIO1_25/FC2_TXD_SCL_MISO_WS/SCT0_OUT2/UTICK_CAP0/PLU_CLKIN) U29.3(~{W}P/SIO2) ; also on sheet 5
SPI_FLASH_PIO0_2: J32.54(IO54) JP27.2 U28.54(PIO0_2/FC3_TXD_SCL_MISO_WS/CTIMER_INP1/SCT0_OUT0/SCT0_GPI2/SEC_PIO0_2) ; also on sheet 5
SPI_FLASH_PIO0_3: J32.55(IO55) JP28.2 U28.55(PIO0_3/FC3_RXD_SDA_MOSI_DATA/CTIMER0_MAT1/SCT0_OUT1/SCT0_GPI3/SEC_PIO0_3) ; also on sheet 5
SPI_FLASH_PIO0_4: J32.57(IO57) JP29.2 U28.57(PIO0_4/CAN0_RD/FC4_SCK/CTIMER_INP12/SCT0_GPI4/FC3_CTS_SDA_SSEL0/SEC_PIO0_4) ; also on sheet 5
SPI_FLASH_PIO0_6: J32.59(IO59) JP30.2 U28.59(PIO0_6/FC3_SCK/CTIMER_INP13/CTIMER4_MAT0/SCT0_GPI6/SEC_PIO0_6) ; also on sheet 5
UART_SPI_EN#: JP9.2 R146.1 U22.9(~{OE}) U24.9(~{OE})
VREFP: C468.1 J32.10(IO10) R65.2 U28.10(VREFP)
XTAL32K_N: C465.1 J32.35(IO35) U28.35(XTAL32K_N) Y3.1
XTAL32K_P: C464.1 J32.34(IO34) U28.34(XTAL32K_P) Y3.2
XTAL32M_N: C463.1 J32.19(IO19) U28.19(XTAL32M_N) Y2.1
XTAL32M_P: C462.1 J32.20(IO20) U28.20(XTAL32M_P) Y2.3
N59397: R132.1 U22.6(A4)
N60020: R133.1 U22.11(B4)
N63149: J18.1(A1) R139.2
N63153: R136.1 R137.1 R141.2
N63221: J18.3(A2) R138.2
N63225: J18.4(B2) R142.1
N63293: J18.5(A3) R140.2
N63337: J18.7(A4) R143.2
N67918: R135.1 U23.4(Y)
N70850: C98.1 JS3.1 R147.2 R150.1 SW4.1 SW4.2
N73960: J18.6(B3) R144.1
N73966: J18.8(B4) R145.1
N74033: J18.2(B1) R141.1
N76712: R130.1 U22.14(B1)
N76718: R131.1 U22.13(B2)

Not connected (* = marked no-connect by the designer): U22 5(A3)* 12(B3)*; U23 1(NC)*

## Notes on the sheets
sheet 8
- Freelink pin: UART0_TX
- Freelink pin: UART0_RX
- tied to MCU and UART connector 1x3
- DIR#  L:B to A, H:A to B
- OD
- CS
- MOSI
- MISO
- SCL
- SCK
- SDA
- master
- slave
- JP9: Open to enable both PMOD SPI and
  LINK2 USB to UART0, short to disable.
- DIR#  L:B to A, H:A to B
sheet 9
- 2.0V/3.3V
- LPC55S06
- 2.0V/3.3V
- 2.0V/3.3V
- <<
- 1.0V
- >>
- Place close to VDD_PMU pin
- SKT 64 QFP SMT 0.5MM 680H AU
- P0_0
- P0_1
- MCU is slave @ISP mode
  MCU is master @ other mode
- P0_2
- P0_3
- P0_4
- P0_5
- P0_6
- P0_7
- P0_8
- P0_10
- P0_9
- P0_11
- P0_12
- P0_13
- P0_14
- P0_15
- P0_16
- P0_18
- P0_19
- P0_20
- P0_21
- P0_22
- P0_23
- P0_24
- P0_25
- P0_26
- P0_27
- P0_28
- P0_29 is RX of MCU
- P0_29
- P0_30
- P0_31
- P1_0
- P1_1
- P1_2
- P1_3
- P1_4
- P1_5
- P1_9
- P1_10
- P1_11
- P1_21
- P1_22
- tied to ACC/CDC/ARD/MIK
- P1_23
- P1_25
- P1_29
- SPI NOR FLASH Mode / SPI Mode
- SPI NOR FLASH
- HS SPI / CAN
- P0_2
- P0_3
- P0_2
- P0_3
- P1_25
- P1_21
- P0_4
- CAN-FD Interface
- HS LSPI Interface
- P0_4
- P0_6
- P0_6
- Package : 8 PIN SOP
sheet 10
- Jumper Table
- REF DES
- JUMPER(DEFAULT)
- PAGE NAME
- JP1
- 1-2
- 03 - System Power
- JP24,JP23
- 1-2
- 04 - Peripheral
- J3,JP12
- OPEN
- 04 - Peripheral
- J11
- OPEN
- 05 - Other Interface
- JP6
- OPEN
- 06 - Link2 MCU
- JP16,JP17,JP15,JP8,JP13
- 1-2
- 07 - Link2 SWD
- JP14,JP7,J17
- OPEN
- 07 - Link2 SWD
- JS4,JS5
- 1-2
- 08 - Link2 ISP
- J18,JS3,JP9
- OPEN
- 08 - Link2 ISP
- JP20,JP21,JP22
- 1-2
- 09 - LPC55S06
- JP25,JP26
- 2-3
- 09 - LPC55S06
- JP28,JP29,JP30,JP27
- OPEN
- 09 - LPC55S06
- DNP Table
- REF DES
- ASSY_OPT
- PAGE NAME
- JS1,SS4,SS3,SS2,SS1
- DNP
- 03 - System Power
- R34,R35,R32,R33
- DNP
- 04 - Peripheral
- JP4
- DNP
- 05 - Other Interface
- R107,R108,R109,R91,R92,J16,
  R151
- DNP
- 06 - Link2 MCU
- R115,R119,R114
- DNP
- 07 - Link2 SWD
- R136
- DNP
- 08 - Link2 ISP
- C464,C462,C465,C19,C463,U29,
  C466,J32
- DNP
- 09 - LPC55S06
